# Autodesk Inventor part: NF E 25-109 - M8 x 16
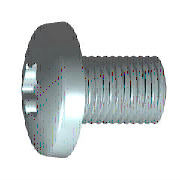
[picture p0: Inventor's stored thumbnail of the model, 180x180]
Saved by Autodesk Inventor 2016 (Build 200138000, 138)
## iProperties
IsCustomPart: 0
Created: 2015-02
Part Number: NF E 25-109 - M8 x 16
Material: Steel, Mild
Description: Hexagon Lobular Socket Pan Head Screw
Document SubType Name: Modeling
Standard: NF E 25-109
Designer: stank
Standards Organization: AFNOR
Language: en-US
Size Designation: M8 x 16
Categories: <MemberInstance><Categories><Category DisplayName="Fasteners" InternalName="e4da775c-781d-43d5-af7c-5136215cf5a6" Mnemonic="FSTN"><Category DisplayName="Bolts"
Density: 7.85 g/cm^3
Appearance: Semi-Polished
Mass: 12.9773 g
Surface Area: 10.5957 cm^2
Volume: 1.65315 cm^3
Author: stank
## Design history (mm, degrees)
sketch "Sketch1"
  geometry: L1 (-1.47, 0)-(16, 0); L2 (16, 0)-(16, 4); L3 (16, 4)-(1.25, 4); L4 (1.25, 4)-(0.483, 3.662); L5 (0.483, 3.662)-(0, 3.662); L6 (0, 3.662)-(0, 8); L7 (0, 8)-(-3.247, 8); L8 (-5.563, 3.344)-(-3.4, 3.344); L9 (-3.4, 3.344)-(-1.47, 0); L10 (-6, 0)-(-1.47, 0); L11 (-18.19, 0)-(55.532, 0) reference; L12 (0, -2)-(0, 12) reference; L13 (1.25, 4)-(0, 4); A1 r 13 centre (7, 0) between (-3.247, 8) and (-5.563, 3.344); A2 r 13 centre (7, 0) between (-5.563, 3.344) and (-6, 0)
  constraints: 22 end point, 4 perpendicular, 4 point on circle, 3 collinear, 2 centre point, 2 parallel, 2 point on line, 1 coincident, 1 horizontal
  dimensions: "d0" = 16 distance between parallel lines of L2 L6 (= NLG); "d1" = 14.75 distance from line of L3.end L2 (= GEL); "d2" = 0.76681 horizontal distance of L4.end L3.end (= GAL); "d3" = 6 distance from line of L10.start L6 (= KOH); "d4" = 2.6 horizontal distance of L10.start L8.end (= INTI); "d5" = 60 deg angle of L9 L1; "d6" = 8 diameter of L3 L1 (= GD); "d7" = 16 diameter of L6.end L1 (= KOD); "d8" = 0 deg angle of L7 L1 (computed from KEWI); "d9" = 6.687 diameter of L8 L1 (= E0); "d10" = 7.32342 diameter of L5 L1 (= BDM); "d11" = 13 radius of A1 (= KR); "d21" = 0.43732 horizontal distance of L8.start L10.start (derived)
revolve "Body" sketch "Sketch1" stored, may be unused: angle "d12" = 90 deg
node "IDS_WORKPLANE{1}"
sketch "Sketch2"
  geometry: L1 (0, -11.2)-(0, 11.2) reference; L2 (11.2, 0)-(-11.2, 0) reference; L3 (0, 0)-(2.233, 3.868); L4 (0, 0)-(3.82, 2.206); C1 r 2.39 at (0, 0); C2 r 3.662 at (0, 0); C3 r 3.662 at (0, 0) reference; A1 r 0.548 centre (3.114, 0) between (3.662, 0) and (3.137, 0.547); A2 r 0.548 centre (1.557, 2.697) between (2.043, 2.443) and (1.095, 2.991); A3 r 1.297 centre (3.193, 1.844) between (2.043, 2.443) and (3.137, 0.547); A4 r 0.548 centre (-1.557, 2.697) between (-1.095, 2.991) and (-2.043, 2.443); A5 r 1.297 centre (0, 3.687) between (-1.095, 2.991) and (1.095, 2.991); A6 r 1.297 centre (-3.193, 1.844) between (-3.137, 0.547) and (-2.043, 2.443); A7 r 0.548 centre (-3.114, 0) between (-3.137, 0.547) and (-3.662, 0); A8 r 0.548 centre (-3.114, 0) between (-3.662, 0) and (-3.137, -0.547); A9 r 1.297 centre (-3.193, -1.844) between (-2.043, -2.443) and (-3.137, -0.547); A10 r 0.548 centre (-1.557, -2.697) between (-2.043, -2.443) and (-1.095, -2.991); A11 r 1.297 centre (0, -3.687) between (1.095, -2.991) and (-1.095, -2.991); A12 r 0.548 centre (1.557, -2.697) between (1.095, -2.991) and (2.043, -2.443); A13 r 1.297 centre (3.193, -1.844) between (3.137, -0.547) and (2.043, -2.443); A14 r 0.548 centre (3.114, 0) between (3.137, -0.547) and (3.662, 0); 2 further points
  constraints: 28 point on circle, 16 centre point, 16 symmetric about line, 10 tangent, 4 end point, 3 point on line, 1 coincident, 10 other
  dimensions: "d14" = 4.78 diameter of C1 (= SW); "d15" = 30 deg angle of L4 L2; "d16" = 60 deg angle of L3 L2; "d27" = 0.548 radius of A4 (= RRK); "d28" = 0.548 radius of A1 (= RRK)
extrude "Slot" join sketch "Sketch2" taper "d17" = 0 deg; stored distance "d19" = 10
workplane "Work Plane2"
body "Solid1"
fillet "Fillet1" dims "d18" = 0.8 (= RR)
feature "Thread" dims "d20" = 14.75 (= GEL), "d22" = 0
other parameters: "GD" = 8 (= NND) [user parameter; used in 1 equation term], "NLG" = 16 [user parameter; used in 1 equation term], "GEL" = 14.75 [user parameter; used in 2 equation terms], "KOD" = 16 [user parameter; used in 1 equation term], "KOH" = 6 [user parameter; used in 2 equation terms], "INTI" = 2.6 [user parameter; used in 1 equation term], "GAL" = 0.76681 (= 0.61345 x PTC) [user parameter; used in 2 equation terms], "KR" = 13 [user parameter; used in 1 equation term], "BDM" = 7.32342 [user parameter; used in 1 equation term], "KEWI" = 0 [user parameter; used in 1 equation term], "SW" = 4.78 [user parameter; used in 1 equation term], "d13" = -5.56268 (= -KOH + d21), "RR" = 0.8 [user parameter; used in 1 equation term], "RRK" = 0.548 [user parameter; used in 2 equation terms], "d26" = 0, "E0" = 6.687 [user parameter; used in 1 equation term], "d32" = 0, "d33" = 0, "GUL" = 0.76681 (= 0.61345 x PTC) [user parameter], "SPD" = 7.0592 (= NND - 1.2269 x GAL) [user parameter], "PHH" = 0 [user parameter], "GD1" = 6.46637 (= THREADDIA - 1.2269 x PTC) [user parameter], "THREADDIA" = 8 [user parameter; used in 1 equation term], "FAWI" = 90 deg [user parameter], "ANG" = 120 deg [user parameter], "TPU" = 8 (computed from PTC) [user parameter], "PTC" = 1.25 [user parameter; used in 4 equation terms], "NND" = 8 [user parameter; used in 2 equation terms], "TOA" = 30 deg [user parameter]
